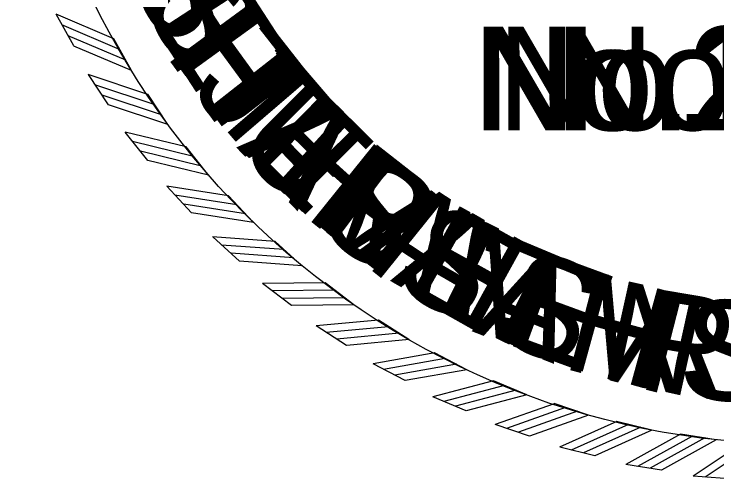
# Model space of a CAD drawing. Extents: x 18 to 14744716, y -5 to 1829144.
# Drawn here: x 17.6844 to 17.7576, y 10.8205 to 10.8689 of the extents above; entities that cross this region are included whole.
import ezdxf

# ---------------------------------------------------------------- set-up
doc = ezdxf.new("R2010")
doc.units = 0
for name, color, linetype in [('B_StampERBB', 7, 'Continuous'), ('B_StampHSS', 7, 'Continuous'), ('B_StampJSB', 7, 'Continuous'), ('B_StampSCR', 7, 'Continuous'), ('B_StampSFH', 7, 'Continuous')]:
    doc.layers.add(name, color=color, linetype=linetype)

msp = doc.modelspace()

# ---------------------------------------------------------------- linework, layer by layer
at = {"layer": 'B_StampERBB'}
for p, q in [((17.690617, 10.865578), (17.688793, 10.868877)), ((17.696618, 10.863018), (17.694789, 10.866325)), ((17.694224, 10.859455), (17.692133, 10.862592)), ((17.700415, 10.857399), (17.698319, 10.860543)), ((17.698324, 10.85365), (17.695981, 10.856604)), ((17.704664, 10.852113), (17.702315, 10.855073)), ((17.702889, 10.848204), (17.70031, 10.850954)), ((17.709334, 10.847195), (17.70675, 10.849952)), ((17.707888, 10.843153), (17.705091, 10.845681)), ((17.714395, 10.84268), (17.711591, 10.845214)), ((17.713288, 10.838533), (17.710291, 10.840821)), ((17.719811, 10.838599), (17.716808, 10.840892)), ((17.725546, 10.834978), (17.722364, 10.837016)), ((17.71905, 10.834374), (17.715875, 10.836407)), ((17.73156, 10.831844), (17.72822, 10.833612)), ((17.725136, 10.830705), (17.721804, 10.832469)), ((17.737812, 10.829217), (17.734338, 10.830703)), ((17.731505, 10.827551), (17.728038, 10.829034)), ((17.74426, 10.827115), (17.740675, 10.828309)), ((17.75086, 10.825553), (17.747188, 10.826447)), ((17.738112, 10.824934), (17.734535, 10.826126)), ((17.757566, 10.824541), (17.753833, 10.825128)), ((17.744912, 10.822872), (17.741249, 10.823764)), ((17.75186, 10.821378), (17.748136, 10.821964)), ((17.758907, 10.820463), (17.755148, 10.82074))]:
    msp.add_line(p, q, dxfattribs=at)
for points in [[(17.694789, 10.866319), (17.688788, 10.868879)], [(17.695386, 10.865215), (17.689386, 10.867774)], [(17.696046, 10.864083), (17.690045, 10.866642)], [(17.696623, 10.863016), (17.690623, 10.865575)], [(17.69832, 10.860538), (17.692129, 10.862593)], [(17.699007, 10.859487), (17.692816, 10.861542)], [(17.699757, 10.858413), (17.693566, 10.860468)], [(17.700421, 10.857397), (17.69423, 10.859452)], [(17.702316, 10.855068), (17.695977, 10.856605)], [(17.703087, 10.854077), (17.696748, 10.855614)], [(17.703924, 10.853069), (17.697584, 10.854606)], [(17.704669, 10.852111), (17.69833, 10.853648)], [(17.706751, 10.849947), (17.700306, 10.850955)], [(17.707601, 10.849022), (17.701156, 10.850031)], [(17.708518, 10.848087), (17.702073, 10.849095)], [(17.70934, 10.847194), (17.702895, 10.848202)], [(17.711593, 10.845209), (17.705087, 10.845681)], [(17.712517, 10.844358), (17.706011, 10.844831)], [(17.713508, 10.843502), (17.707002, 10.843974)], [(17.714401, 10.84268), (17.707895, 10.843152)], [(17.71681, 10.840887), (17.710287, 10.840821)], [(17.717801, 10.840116), (17.711278, 10.840049)], [(17.718859, 10.839344), (17.712336, 10.839278)], [(17.719817, 10.838599), (17.713294, 10.838532)], [(17.722366, 10.837011), (17.715871, 10.836406)], [(17.723417, 10.836324), (17.716922, 10.835719)], [(17.724536, 10.835642), (17.718041, 10.835038)], [(17.725552, 10.834979), (17.719056, 10.834374)], [(17.728223, 10.833607), (17.7218, 10.832468)], [(17.729327, 10.833009), (17.722904, 10.83187)], [(17.730498, 10.832422), (17.724075, 10.831283)], [(17.731566, 10.831845), (17.725143, 10.830706)], [(17.734341, 10.830698), (17.728034, 10.829033)], [(17.735491, 10.830194), (17.729184, 10.828528)], [(17.736707, 10.829706), (17.7304, 10.82804)], [(17.737818, 10.829218), (17.731511, 10.827552)], [(17.740679, 10.828305), (17.734531, 10.826124)], [(17.741867, 10.827897), (17.735719, 10.825716)], [(17.743118, 10.827511), (17.73697, 10.82533)], [(17.744266, 10.827117), (17.738118, 10.824936)], [(17.747192, 10.826443), (17.741245, 10.823762)], [(17.74841, 10.826135), (17.742463, 10.823454)], [(17.749689, 10.825853), (17.743742, 10.823172)], [(17.750865, 10.825555), (17.744918, 10.822874)], [(17.753837, 10.825125), (17.748132, 10.821962)], [(17.755076, 10.824918), (17.749371, 10.821755)], [(17.756374, 10.824743), (17.750669, 10.82158)], [(17.757571, 10.824544), (17.751866, 10.821381)], [(17.760568, 10.824361), (17.755144, 10.820737)], [(17.76182, 10.824257), (17.756396, 10.820634)]]:
    msp.add_lwpolyline(points, dxfattribs=at)
at = {"layer": 'B_StampHSS'}
for p, q in [((17.690617, 10.865578), (17.688793, 10.868877)), ((17.696618, 10.863018), (17.694789, 10.866325)), ((17.694224, 10.859455), (17.692133, 10.862592)), ((17.700415, 10.857399), (17.698319, 10.860543)), ((17.698324, 10.85365), (17.695981, 10.856604)), ((17.704664, 10.852113), (17.702315, 10.855073)), ((17.702889, 10.848204), (17.70031, 10.850954)), ((17.709334, 10.847195), (17.70675, 10.849952)), ((17.707888, 10.843153), (17.705091, 10.845681)), ((17.714395, 10.84268), (17.711591, 10.845214)), ((17.713288, 10.838533), (17.710291, 10.840821)), ((17.719811, 10.838599), (17.716808, 10.840892)), ((17.725546, 10.834978), (17.722364, 10.837016)), ((17.71905, 10.834374), (17.715875, 10.836407)), ((17.73156, 10.831844), (17.72822, 10.833612)), ((17.725136, 10.830705), (17.721804, 10.832469)), ((17.737812, 10.829217), (17.734338, 10.830703)), ((17.731505, 10.827551), (17.728038, 10.829034)), ((17.74426, 10.827115), (17.740675, 10.828309)), ((17.75086, 10.825553), (17.747188, 10.826447)), ((17.738112, 10.824934), (17.734535, 10.826126)), ((17.757566, 10.824541), (17.753833, 10.825128)), ((17.744912, 10.822872), (17.741249, 10.823764)), ((17.75186, 10.821378), (17.748136, 10.821964)), ((17.758907, 10.820463), (17.755148, 10.82074))]:
    msp.add_line(p, q, dxfattribs=at)
for points in [[(17.694789, 10.866319), (17.688788, 10.868879)], [(17.695386, 10.865215), (17.689386, 10.867774)], [(17.696046, 10.864083), (17.690045, 10.866642)], [(17.696623, 10.863016), (17.690623, 10.865575)], [(17.69832, 10.860538), (17.692129, 10.862593)], [(17.699007, 10.859487), (17.692816, 10.861542)], [(17.699757, 10.858413), (17.693566, 10.860468)], [(17.700421, 10.857397), (17.69423, 10.859452)], [(17.702316, 10.855068), (17.695977, 10.856605)], [(17.703087, 10.854077), (17.696748, 10.855614)], [(17.703924, 10.853069), (17.697584, 10.854606)], [(17.704669, 10.852111), (17.69833, 10.853648)], [(17.706751, 10.849947), (17.700306, 10.850955)], [(17.707601, 10.849022), (17.701156, 10.850031)], [(17.708518, 10.848087), (17.702073, 10.849095)], [(17.70934, 10.847194), (17.702895, 10.848202)], [(17.711593, 10.845209), (17.705087, 10.845681)], [(17.712517, 10.844358), (17.706011, 10.844831)], [(17.713508, 10.843502), (17.707002, 10.843974)], [(17.714401, 10.84268), (17.707895, 10.843152)], [(17.71681, 10.840887), (17.710287, 10.840821)], [(17.717801, 10.840116), (17.711278, 10.840049)], [(17.718859, 10.839344), (17.712336, 10.839278)], [(17.719817, 10.838599), (17.713294, 10.838532)], [(17.722366, 10.837011), (17.715871, 10.836406)], [(17.723417, 10.836324), (17.716922, 10.835719)], [(17.724536, 10.835642), (17.718041, 10.835038)], [(17.725552, 10.834979), (17.719056, 10.834374)], [(17.728223, 10.833607), (17.7218, 10.832468)], [(17.729327, 10.833009), (17.722904, 10.83187)], [(17.730498, 10.832422), (17.724075, 10.831283)], [(17.731566, 10.831845), (17.725143, 10.830706)], [(17.734341, 10.830698), (17.728034, 10.829033)], [(17.735491, 10.830194), (17.729184, 10.828528)], [(17.736707, 10.829706), (17.7304, 10.82804)], [(17.737818, 10.829218), (17.731511, 10.827552)], [(17.740679, 10.828305), (17.734531, 10.826124)], [(17.741867, 10.827897), (17.735719, 10.825716)], [(17.743118, 10.827511), (17.73697, 10.82533)], [(17.744266, 10.827117), (17.738118, 10.824936)], [(17.747192, 10.826443), (17.741245, 10.823762)], [(17.74841, 10.826135), (17.742463, 10.823454)], [(17.749689, 10.825853), (17.743742, 10.823172)], [(17.750865, 10.825555), (17.744918, 10.822874)], [(17.753837, 10.825125), (17.748132, 10.821962)], [(17.755076, 10.824918), (17.749371, 10.821755)], [(17.756374, 10.824743), (17.750669, 10.82158)], [(17.757571, 10.824544), (17.751866, 10.821381)], [(17.760568, 10.824361), (17.755144, 10.820737)], [(17.76182, 10.824257), (17.756396, 10.820634)]]:
    msp.add_lwpolyline(points, dxfattribs=at)
at = {"layer": 'B_StampJSB'}
for p, q in [((17.690617, 10.865578), (17.688793, 10.868877)), ((17.696618, 10.863018), (17.694789, 10.866325)), ((17.694224, 10.859455), (17.692133, 10.862592)), ((17.700415, 10.857399), (17.698319, 10.860543)), ((17.698324, 10.85365), (17.695981, 10.856604)), ((17.704664, 10.852113), (17.702315, 10.855073)), ((17.702889, 10.848204), (17.70031, 10.850954)), ((17.709334, 10.847195), (17.70675, 10.849952)), ((17.707888, 10.843153), (17.705091, 10.845681)), ((17.714395, 10.84268), (17.711591, 10.845214)), ((17.713288, 10.838533), (17.710291, 10.840821)), ((17.719811, 10.838599), (17.716808, 10.840892)), ((17.725546, 10.834978), (17.722364, 10.837016)), ((17.71905, 10.834374), (17.715875, 10.836407)), ((17.73156, 10.831844), (17.72822, 10.833612)), ((17.725136, 10.830705), (17.721804, 10.832469)), ((17.737812, 10.829217), (17.734338, 10.830703)), ((17.731505, 10.827551), (17.728038, 10.829034)), ((17.74426, 10.827115), (17.740675, 10.828309)), ((17.75086, 10.825553), (17.747188, 10.826447)), ((17.738112, 10.824934), (17.734535, 10.826126)), ((17.757566, 10.824541), (17.753833, 10.825128)), ((17.744912, 10.822872), (17.741249, 10.823764)), ((17.75186, 10.821378), (17.748136, 10.821964)), ((17.758907, 10.820463), (17.755148, 10.82074))]:
    msp.add_line(p, q, dxfattribs=at)
for points in [[(17.694789, 10.866319), (17.688788, 10.868879)], [(17.695386, 10.865215), (17.689386, 10.867774)], [(17.696046, 10.864083), (17.690045, 10.866642)], [(17.696623, 10.863016), (17.690623, 10.865575)], [(17.69832, 10.860538), (17.692129, 10.862593)], [(17.699007, 10.859487), (17.692816, 10.861542)], [(17.699757, 10.858413), (17.693566, 10.860468)], [(17.700421, 10.857397), (17.69423, 10.859452)], [(17.702316, 10.855068), (17.695977, 10.856605)], [(17.703087, 10.854077), (17.696748, 10.855614)], [(17.703924, 10.853069), (17.697584, 10.854606)], [(17.704669, 10.852111), (17.69833, 10.853648)], [(17.706751, 10.849947), (17.700306, 10.850955)], [(17.707601, 10.849022), (17.701156, 10.850031)], [(17.708518, 10.848087), (17.702073, 10.849095)], [(17.70934, 10.847194), (17.702895, 10.848202)], [(17.711593, 10.845209), (17.705087, 10.845681)], [(17.712517, 10.844358), (17.706011, 10.844831)], [(17.713508, 10.843502), (17.707002, 10.843974)], [(17.714401, 10.84268), (17.707895, 10.843152)], [(17.71681, 10.840887), (17.710287, 10.840821)], [(17.717801, 10.840116), (17.711278, 10.840049)], [(17.718859, 10.839344), (17.712336, 10.839278)], [(17.719817, 10.838599), (17.713294, 10.838532)], [(17.722366, 10.837011), (17.715871, 10.836406)], [(17.723417, 10.836324), (17.716922, 10.835719)], [(17.724536, 10.835642), (17.718041, 10.835038)], [(17.725552, 10.834979), (17.719056, 10.834374)], [(17.728223, 10.833607), (17.7218, 10.832468)], [(17.729327, 10.833009), (17.722904, 10.83187)], [(17.730498, 10.832422), (17.724075, 10.831283)], [(17.731566, 10.831845), (17.725143, 10.830706)], [(17.734341, 10.830698), (17.728034, 10.829033)], [(17.735491, 10.830194), (17.729184, 10.828528)], [(17.736707, 10.829706), (17.7304, 10.82804)], [(17.737818, 10.829218), (17.731511, 10.827552)], [(17.740679, 10.828305), (17.734531, 10.826124)], [(17.741867, 10.827897), (17.735719, 10.825716)], [(17.743118, 10.827511), (17.73697, 10.82533)], [(17.744266, 10.827117), (17.738118, 10.824936)], [(17.747192, 10.826443), (17.741245, 10.823762)], [(17.74841, 10.826135), (17.742463, 10.823454)], [(17.749689, 10.825853), (17.743742, 10.823172)], [(17.750865, 10.825555), (17.744918, 10.822874)], [(17.753837, 10.825125), (17.748132, 10.821962)], [(17.755076, 10.824918), (17.749371, 10.821755)], [(17.756374, 10.824743), (17.750669, 10.82158)], [(17.757571, 10.824544), (17.751866, 10.821381)], [(17.760568, 10.824361), (17.755144, 10.820737)], [(17.76182, 10.824257), (17.756396, 10.820634)]]:
    msp.add_lwpolyline(points, dxfattribs=at)
msp.add_circle((17.766447, 10.906117), 0.082054, dxfattribs=at)
at = {"layer": 'B_StampSCR'}
for p, q in [((17.690617, 10.865578), (17.688793, 10.868877)), ((17.696618, 10.863018), (17.694789, 10.866325)), ((17.694224, 10.859455), (17.692133, 10.862592)), ((17.700415, 10.857399), (17.698319, 10.860543)), ((17.698324, 10.85365), (17.695981, 10.856604)), ((17.704664, 10.852113), (17.702315, 10.855073)), ((17.702889, 10.848204), (17.70031, 10.850954)), ((17.709334, 10.847195), (17.70675, 10.849952)), ((17.707888, 10.843153), (17.705091, 10.845681)), ((17.714395, 10.84268), (17.711591, 10.845214)), ((17.713288, 10.838533), (17.710291, 10.840821)), ((17.719811, 10.838599), (17.716808, 10.840892)), ((17.725546, 10.834978), (17.722364, 10.837016)), ((17.71905, 10.834374), (17.715875, 10.836407)), ((17.73156, 10.831844), (17.72822, 10.833612)), ((17.725136, 10.830705), (17.721804, 10.832469)), ((17.737812, 10.829217), (17.734338, 10.830703)), ((17.731505, 10.827551), (17.728038, 10.829034)), ((17.74426, 10.827115), (17.740675, 10.828309)), ((17.75086, 10.825553), (17.747188, 10.826447)), ((17.738112, 10.824934), (17.734535, 10.826126)), ((17.757566, 10.824541), (17.753833, 10.825128)), ((17.744912, 10.822872), (17.741249, 10.823764)), ((17.75186, 10.821378), (17.748136, 10.821964)), ((17.758907, 10.820463), (17.755148, 10.82074))]:
    msp.add_line(p, q, dxfattribs=at)
for points in [[(17.694789, 10.866319), (17.688788, 10.868879)], [(17.695386, 10.865215), (17.689386, 10.867774)], [(17.696046, 10.864083), (17.690045, 10.866642)], [(17.696623, 10.863016), (17.690623, 10.865575)], [(17.69832, 10.860538), (17.692129, 10.862593)], [(17.699007, 10.859487), (17.692816, 10.861542)], [(17.699757, 10.858413), (17.693566, 10.860468)], [(17.700421, 10.857397), (17.69423, 10.859452)], [(17.702316, 10.855068), (17.695977, 10.856605)], [(17.703087, 10.854077), (17.696748, 10.855614)], [(17.703924, 10.853069), (17.697584, 10.854606)], [(17.704669, 10.852111), (17.69833, 10.853648)], [(17.706751, 10.849947), (17.700306, 10.850955)], [(17.707601, 10.849022), (17.701156, 10.850031)], [(17.708518, 10.848087), (17.702073, 10.849095)], [(17.70934, 10.847194), (17.702895, 10.848202)], [(17.711593, 10.845209), (17.705087, 10.845681)], [(17.712517, 10.844358), (17.706011, 10.844831)], [(17.713508, 10.843502), (17.707002, 10.843974)], [(17.714401, 10.84268), (17.707895, 10.843152)], [(17.71681, 10.840887), (17.710287, 10.840821)], [(17.717801, 10.840116), (17.711278, 10.840049)], [(17.718859, 10.839344), (17.712336, 10.839278)], [(17.719817, 10.838599), (17.713294, 10.838532)], [(17.722366, 10.837011), (17.715871, 10.836406)], [(17.723417, 10.836324), (17.716922, 10.835719)], [(17.724536, 10.835642), (17.718041, 10.835038)], [(17.725552, 10.834979), (17.719056, 10.834374)], [(17.728223, 10.833607), (17.7218, 10.832468)], [(17.729327, 10.833009), (17.722904, 10.83187)], [(17.730498, 10.832422), (17.724075, 10.831283)], [(17.731566, 10.831845), (17.725143, 10.830706)], [(17.734341, 10.830698), (17.728034, 10.829033)], [(17.735491, 10.830194), (17.729184, 10.828528)], [(17.736707, 10.829706), (17.7304, 10.82804)], [(17.737818, 10.829218), (17.731511, 10.827552)], [(17.740679, 10.828305), (17.734531, 10.826124)], [(17.741867, 10.827897), (17.735719, 10.825716)], [(17.743118, 10.827511), (17.73697, 10.82533)], [(17.744266, 10.827117), (17.738118, 10.824936)], [(17.747192, 10.826443), (17.741245, 10.823762)], [(17.74841, 10.826135), (17.742463, 10.823454)], [(17.749689, 10.825853), (17.743742, 10.823172)], [(17.750865, 10.825555), (17.744918, 10.822874)], [(17.753837, 10.825125), (17.748132, 10.821962)], [(17.755076, 10.824918), (17.749371, 10.821755)], [(17.756374, 10.824743), (17.750669, 10.82158)], [(17.757571, 10.824544), (17.751866, 10.821381)], [(17.760568, 10.824361), (17.755144, 10.820737)], [(17.76182, 10.824257), (17.756396, 10.820634)]]:
    msp.add_lwpolyline(points, dxfattribs=at)
at = {"layer": 'B_StampSFH'}
for p, q in [((17.690617, 10.865578), (17.688793, 10.868877)), ((17.696618, 10.863018), (17.694789, 10.866325)), ((17.694224, 10.859455), (17.692133, 10.862592)), ((17.700415, 10.857399), (17.698319, 10.860543)), ((17.698324, 10.85365), (17.695981, 10.856604)), ((17.704664, 10.852113), (17.702315, 10.855073)), ((17.702889, 10.848204), (17.70031, 10.850954)), ((17.709334, 10.847195), (17.70675, 10.849952)), ((17.707888, 10.843153), (17.705091, 10.845681)), ((17.714395, 10.84268), (17.711591, 10.845214)), ((17.713288, 10.838533), (17.710291, 10.840821)), ((17.719811, 10.838599), (17.716808, 10.840892)), ((17.725546, 10.834978), (17.722364, 10.837016)), ((17.71905, 10.834374), (17.715875, 10.836407)), ((17.73156, 10.831844), (17.72822, 10.833612)), ((17.725136, 10.830705), (17.721804, 10.832469)), ((17.737812, 10.829217), (17.734338, 10.830703)), ((17.731505, 10.827551), (17.728038, 10.829034)), ((17.74426, 10.827115), (17.740675, 10.828309)), ((17.75086, 10.825553), (17.747188, 10.826447)), ((17.738112, 10.824934), (17.734535, 10.826126)), ((17.757566, 10.824541), (17.753833, 10.825128)), ((17.744912, 10.822872), (17.741249, 10.823764)), ((17.75186, 10.821378), (17.748136, 10.821964)), ((17.758907, 10.820463), (17.755148, 10.82074))]:
    msp.add_line(p, q, dxfattribs=at)
for points in [[(17.694789, 10.866319), (17.688788, 10.868879)], [(17.695386, 10.865215), (17.689386, 10.867774)], [(17.696046, 10.864083), (17.690045, 10.866642)], [(17.696623, 10.863016), (17.690623, 10.865575)], [(17.69832, 10.860538), (17.692129, 10.862593)], [(17.699007, 10.859487), (17.692816, 10.861542)], [(17.699757, 10.858413), (17.693566, 10.860468)], [(17.700421, 10.857397), (17.69423, 10.859452)], [(17.702316, 10.855068), (17.695977, 10.856605)], [(17.703087, 10.854077), (17.696748, 10.855614)], [(17.703924, 10.853069), (17.697584, 10.854606)], [(17.704669, 10.852111), (17.69833, 10.853648)], [(17.706751, 10.849947), (17.700306, 10.850955)], [(17.707601, 10.849022), (17.701156, 10.850031)], [(17.708518, 10.848087), (17.702073, 10.849095)], [(17.70934, 10.847194), (17.702895, 10.848202)], [(17.711593, 10.845209), (17.705087, 10.845681)], [(17.712517, 10.844358), (17.706011, 10.844831)], [(17.713508, 10.843502), (17.707002, 10.843974)], [(17.714401, 10.84268), (17.707895, 10.843152)], [(17.71681, 10.840887), (17.710287, 10.840821)], [(17.717801, 10.840116), (17.711278, 10.840049)], [(17.718859, 10.839344), (17.712336, 10.839278)], [(17.719817, 10.838599), (17.713294, 10.838532)], [(17.722366, 10.837011), (17.715871, 10.836406)], [(17.723417, 10.836324), (17.716922, 10.835719)], [(17.724536, 10.835642), (17.718041, 10.835038)], [(17.725552, 10.834979), (17.719056, 10.834374)], [(17.728223, 10.833607), (17.7218, 10.832468)], [(17.729327, 10.833009), (17.722904, 10.83187)], [(17.730498, 10.832422), (17.724075, 10.831283)], [(17.731566, 10.831845), (17.725143, 10.830706)], [(17.734341, 10.830698), (17.728034, 10.829033)], [(17.735491, 10.830194), (17.729184, 10.828528)], [(17.736707, 10.829706), (17.7304, 10.82804)], [(17.737818, 10.829218), (17.731511, 10.827552)], [(17.740679, 10.828305), (17.734531, 10.826124)], [(17.741867, 10.827897), (17.735719, 10.825716)], [(17.743118, 10.827511), (17.73697, 10.82533)], [(17.744266, 10.827117), (17.738118, 10.824936)], [(17.747192, 10.826443), (17.741245, 10.823762)], [(17.74841, 10.826135), (17.742463, 10.823454)], [(17.749689, 10.825853), (17.743742, 10.823172)], [(17.750865, 10.825555), (17.744918, 10.822874)], [(17.753837, 10.825125), (17.748132, 10.821962)], [(17.755076, 10.824918), (17.749371, 10.821755)], [(17.756374, 10.824743), (17.750669, 10.82158)], [(17.757571, 10.824544), (17.751866, 10.821381)], [(17.760568, 10.824361), (17.755144, 10.820737)], [(17.76182, 10.824257), (17.756396, 10.820634)]]:
    msp.add_lwpolyline(points, dxfattribs=at)

# ---------------------------------------------------------------- texts
at = {"layer": 'B_StampERBB'}
for s, rotation, p in [('E', 302.98727, (17.698628, 10.868056)), ('T', 310.64808, (17.704308, 10.859307)), ('H', 317.94409, (17.710757, 10.851748)), ('A', 326.6993, (17.719684, 10.843849)), ('N', 333.99531, (17.727972, 10.838368)), ('R', 350.41133, (17.748698, 10.830153))]:
    msp.add_text(s, height=0.010417, rotation=rotation, dxfattribs=at).set_placement(p)
msp.add_text('No.20113', height=0.010794, dxfattribs=at).set_placement((17.732143, 10.856805))
at = {"layer": 'B_StampHSS'}
for s, rotation, p in [('H', 306.22623, (17.699998, 10.864839)), ('U', 314.9716, (17.707049, 10.855218)), ('S', 323.71697, (17.71548, 10.846781)), ('S', 331.00477, (17.72342, 10.840797)), ('A', 338.29258, (17.732056, 10.835869)), ('M', 345.58039, (17.741246, 10.832075))]:
    msp.add_text(s, height=0.010417, rotation=rotation, dxfattribs=at).set_placement(p)
msp.add_text('No.18919', height=0.010794, dxfattribs=at).set_placement((17.732571, 10.856805))
at = {"layer": 'B_StampJSB'}
msp.add_text('No.5343 ', height=0.010794, dxfattribs=at).set_placement((17.740706, 10.856805))
for s, rotation, p in [('J', 308.00316, (17.70263, 10.861288)), ('A', 313.8414, (17.707521, 10.855029)), ('M', 321.1392, (17.714488, 10.847958)), ('E', 330.62635, (17.724784, 10.840189)), ('S', 338.28904, (17.733947, 10.835222)), ('S', 353.24953, (17.753351, 10.829236))]:
    msp.add_text(s, height=0.010417, rotation=rotation, dxfattribs=at).set_placement(p)
at = {"layer": 'B_StampSCR'}
for s, rotation, p in [('S', 298.60966, (17.696041, 10.873154)), ('H', 305.90567, (17.700799, 10.864433)), ('A', 314.66089, (17.707911, 10.854871)), ('R', 321.95689, (17.714894, 10.847806)), ('A', 329.98251, (17.723542, 10.841128)), ('T', 337.27851, (17.732144, 10.836159)), ('H', 344.57452, (17.741307, 10.832323))]:
    msp.add_text(s, height=0.010417, rotation=rotation, dxfattribs=at).set_placement(p)
msp.add_text('No.19317', height=0.010794, dxfattribs=at).set_placement((17.732143, 10.856805))
at = {"layer": 'B_StampSFH'}
for s, rotation, p in [('S', 300.79847, (17.697351, 10.870475)), ('T', 308.09448, (17.702438, 10.861943)), ('E', 315.39049, (17.708568, 10.854125)), ('P', 323.0513, (17.716017, 10.846825)), ('H', 331.07691, (17.724791, 10.840314)), ('E', 339.83212, (17.735295, 10.834684)), ('N', 347.49293, (17.745097, 10.83112))]:
    msp.add_text(s, height=0.010417, rotation=rotation, dxfattribs=at).set_placement(p)
msp.add_text('No.14501', height=0.010794, dxfattribs=at).set_placement((17.734712, 10.856805))

doc.saveas('drawing.dxf')
